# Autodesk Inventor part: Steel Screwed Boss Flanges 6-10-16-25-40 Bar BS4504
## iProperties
Created: 2005-02
Part Number: Steel Screwed Boss Flanges 6-10-16-25-40 Bar BS4504
Material: Steel, Mild
Document SubType Name: Modeling
Designer: Robert Thomas
Manufacturer: Standard
Standards Organization: Custom
Description: Steel Screwed Boss Flanges
SPECIFICATION: BS 4504 / EN1092-1:2001(E)
Manufacturer: Not Specified
Manufacturer's Number: Not Specified
PRESSURE: 10 & 16 bar
Nom: 80.000 mm
PipeOD: 88.900 mm
FlangeOD: 200.000 mm
FlangeTHK: 24.000 mm
RaisedFaceTHK: 3.000 mm
RaisedFaceOD: 138.000 mm
Height: 40.000 mm
NeckHeight: 12.000 mm
NeckBaseOD: 118.000 mm
NeckRad: 8.000 mm
HoleDIA: 18.000 mm
HolePCD: 160.000 mm
HoleNo: 8.000 ul
HoleANGLE: 22.50 deg
Author: Robert Thomas
Revision Number: A.1
Title: Steel Screwed Boss Flanges EN1092-1:2001(E)
Subject: 10 & 16 Bar Nom Pressure (Table 9)
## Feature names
1. Revolution1
2. Hole1
3. Circular Pattern1
